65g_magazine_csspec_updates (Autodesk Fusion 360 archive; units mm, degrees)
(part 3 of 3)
extrude "Extrude31" add of existing geometry blind 0.6
extrude "Extrude32" add of existing geometry blind 0.6
fillet "Fillet39" radius 1.5 2 1
fillet "Fillet40" radius 1
fillet "Fillet41" radius 1
fillet "Fillet42" radius 3
fillet "Fillet45" radius 1
fillet "Fillet43" radius 0.5
sketch "Sketch28" plane through (0, 0, 0) normal (0, -1, 0) x axis (1, 0, 0)
  line L1 (0.42, 0.9275) -> (20.28, 0.9275)
  line L2 (-0.58, -35.6726) -> (-0.58, -0.0725)
  line L3 (2.42, -52.4025) -> (2.42, -45)
  line L4 (14.35, -56.3325) -> (6.35, -56.3325)
  line L5 (18.28, -45) -> (18.28, -52.4025)
  line L6 (21.28, -0.0725) -> (21.28, -35.6726)
  line L7 (21.28, -0.0725) -> (-0.58, -0.0725)
  line L8 (6.35, -56.3325) -> (14.35, -56.3325)
  line L9 (10.35, -33.0725) -> (10.35, 0.9275)
  arc A1 centre (12.35, -35.6726) radius 12.93 clockwise from (1.8444, -43.2103) to (-0.58, -35.6726)
  arc A2 centre (-0.65, -45) radius 3.07 clockwise from (1.8444, -43.2103) to (2.42, -45)
  arc A3 centre (6.35, -52.4025) radius 3.93 clockwise from (6.35, -56.3325) to (2.42, -52.4025)
  arc A4 centre (14.35, -52.4025) radius 3.93 clockwise from (18.28, -52.4025) to (14.35, -56.3325)
  arc A5 centre (21.35, -45) radius 3.07 clockwise from (18.28, -45) to (18.8556, -43.2103)
  arc A6 centre (8.35, -35.6726) radius 12.93 clockwise from (21.28, -35.6726) to (18.8556, -43.2103)
  arc A7 centre (0.42, -0.0725) radius 1 clockwise from (-0.58, -0.0725) to (0.42, 0.9275)
  arc A8 centre (20.28, -0.0725) radius 1 clockwise from (20.28, 0.9275) to (21.28, -0.0725)
  point P3 (-0.58, -0.0725)
  point P20 (-0.58, -0.0725)
  point P2 (21.28, -0.0725)
  point P21 (21.28, -0.0725)
  point P12 (14.35, -56.3325)
  point P22 (14.35, -56.3325)
  point P10 (6.35, -56.3325)
  point P23 (6.35, -56.3325)
  point P24 (10.35, 0.9275)
  point P25 (10.35, -33.0725)
  coincident P3 P20
  coincident P2 P21
  coincident P12 P22
  coincident P10 P23
  midpoint L1 P24
  perpendicular L1 L9
  dimension "d411" distance P24 P25 = 34
sketch "Sketch29" plane through (10.35, 0, -28.2025) normal (0, -1, 0) x axis (1, 0, 0)
  line L1 (-10.93, -7.4701) -> (-10.93, 28.13)
  line L2 (-7.93, -24.2) -> (-7.93, -16.7975)
  line L3 (4, -28.13) -> (-4, -28.13)
  line L4 (7.93, -16.7975) -> (7.93, -24.2)
  line L5 (10.93, 28.13) -> (10.93, -7.4701)
  line L6 (-9.93, 29.13) -> (9.93, 29.13)
  line L7 (-4.072, 3.603) -> (4.072, 3.603)
  line L8 (4.072, 3.603) -> (4.072, -7.4701)
  line L9 (-4.072, -7.4701) -> (-4.072, 3.603)
  line L10 (-4.072, -2.9502) -> (4.072, -2.9502)
  arc A1 centre (-9.93, 28.13) radius 1 clockwise from (-10.93, 28.13) to (-9.93, 29.13)
  arc A2 centre (2, -7.4701) radius 12.93 clockwise from (-8.5056, -15.0078) to (-10.93, -7.4701)
  arc A3 centre (-11, -16.7975) radius 3.07 clockwise from (-8.5056, -15.0078) to (-7.93, -16.7975)
  arc A4 centre (-4, -24.2) radius 3.93 clockwise from (-4, -28.13) to (-7.93, -24.2)
  arc A5 centre (4, -24.2) radius 3.93 clockwise from (7.93, -24.2) to (4, -28.13)
  arc A6 centre (11, -16.7975) radius 3.07 clockwise from (7.93, -16.7975) to (8.5056, -15.0078)
  arc A7 centre (-2, -7.4701) radius 12.93 clockwise from (10.93, -7.4701) to (8.5056, -15.0078)
  arc A8 centre (9.93, 28.13) radius 1 clockwise from (9.93, 29.13) to (10.93, 28.13)
  dimension "d417" = -6.5532
fillet "Fillet44" radius 0.5
remove_body "RemoveBody1"
extrude "Extrude33" add sketch "Sketch29" profile of L7 L8 L9 L10 along normal blind 2
fillet "Fillet46" radius 1.5 0.5
fillet "Fillet34" radius 1
extrude "Extrude25" add sketch "extruded features z" profile of L11 L17 L18 L19 L20 to an object
extrude "Extrude24" add sketch "extruded features z" profile of L11 L17 L18 L19 L20 to an object
named bodies: "follower", "floor plate"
